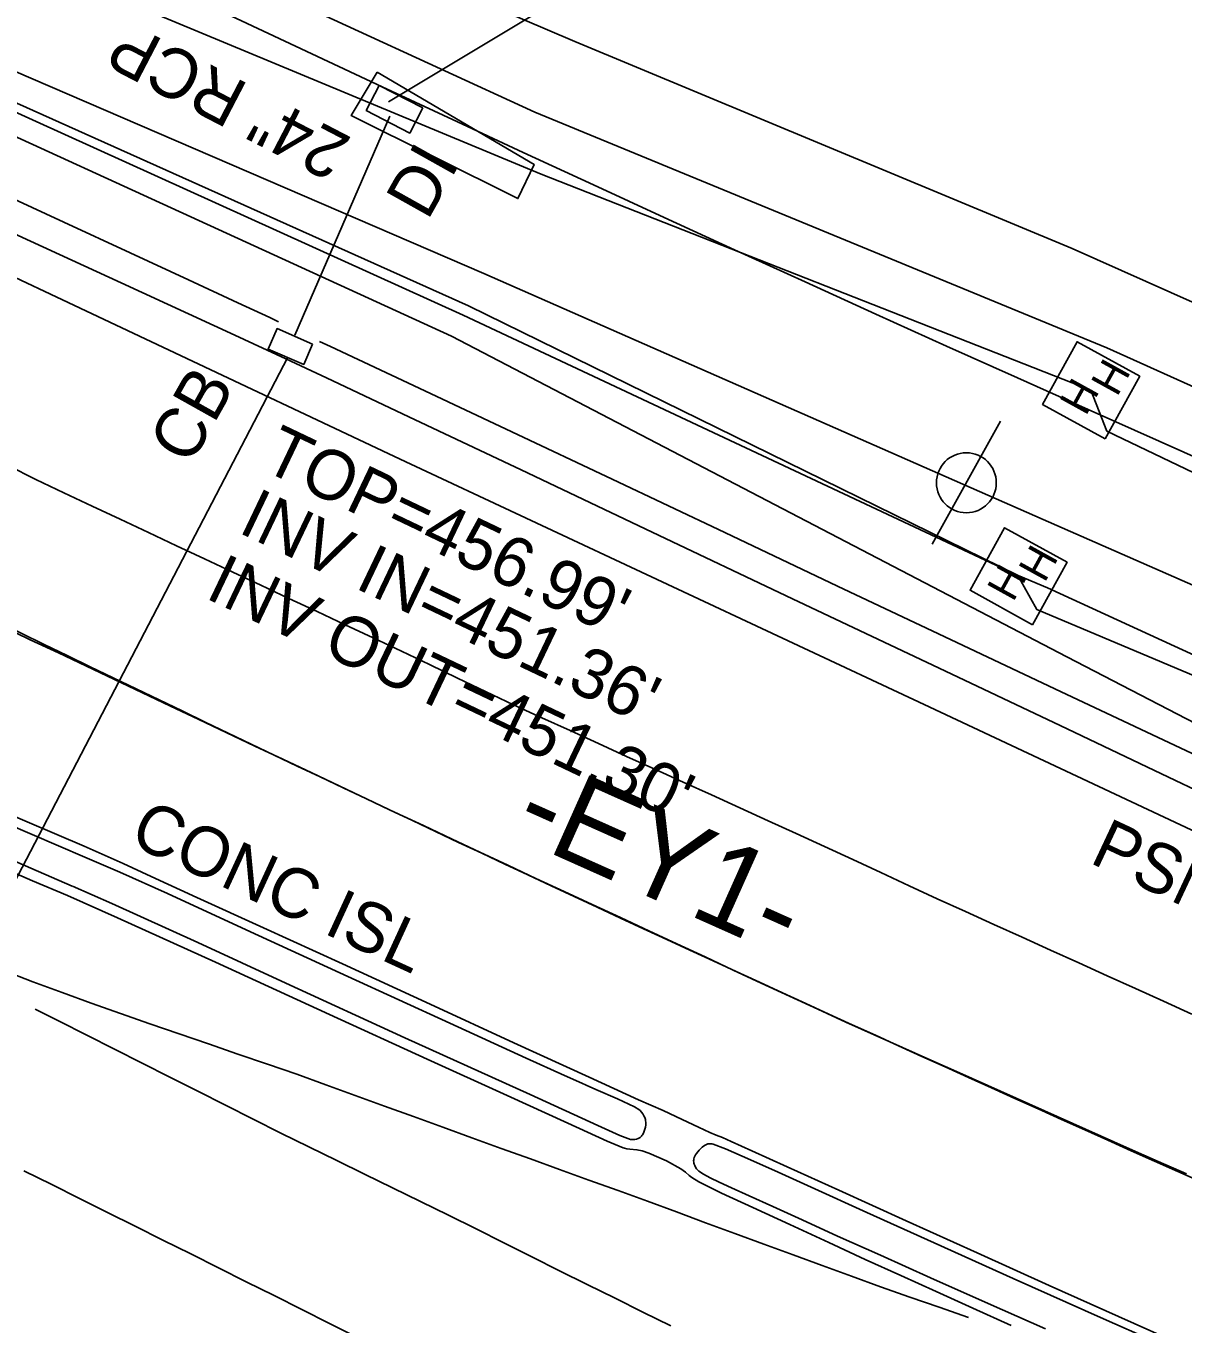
# Model space of a CAD drawing. Extents: x 2074109 to 2077820, y 741079 to 746031.
# Drawn here: x 2076288.2 to 2076381.3, y 742928.4 to 743032.9 of the extents above; entities that cross this region are included whole.
import ezdxf

# ---------------------------------------------------------------- set-up
doc = ezdxf.new("R2010")
doc.units = 0
for name, color, linetype in [('Exist Horizontal Alignment', 7, 'Continuous'), ('Exist Horizontal Alignment Direction Label', 7, 'Continuous'), ('Exist Right of Way Line', 7, 'Continuous'), ('Exist Roads Curbs', 7, 'Continuous'), ('Exist Roads Curbs Text', 7, 'Continuous'), ('Exist Roads EOP', 7, 'Continuous'), ('Exist Roads EOT', 7, 'Continuous'), ('Exist Structure Minor Catch Basin', 7, 'Continuous'), ('Exist Structure Minor Catch Basin Text', 7, 'Continuous'), ('Exist Structure Minor Catch Basin Top Elevation', 7, 'Continuous'), ('Exist Structure Minor Drop Inlet', 7, 'Continuous'), ('Exist Structure Minor Drop Inlet Text', 7, 'Continuous'), ('Exist Structure Minor Paved Ditch or Gutter', 7, 'Continuous'), ('Exist Structure Minor Pipes RCP 24 Inch', 7, 'Continuous'), ('Exist Structure Minor Pipes RCP 24 Inch Invert', 7, 'Continuous'), ('Exist Structure Minor Pipes RCP 24 Inch Text', 7, 'Continuous'), ('Exist Utilities Gas UG Line SUE LOS B', 7, 'Continuous'), ('Exist Utilities Gas UG Line SUE LOS B Text', 7, 'Continuous'), ('Exist Utilities Telephone Pole CELL', 7, 'Continuous'), ('Exist Utilities Telephone UG Conduit SUE LOS B', 7, 'Continuous'), ('Exist Utilities Telephone UG FO SUE LOS B', 7, 'Continuous'), ('Exist Utilities TV Hand Hole CELL', 7, 'Continuous'), ('Exist Utilities TV UG FO Cable SUE LOS B', 7, 'Continuous'), ('Exist Utilities Water UG Line SUE LOS B', 7, 'Continuous'), ('Exist Vegetation Woods Line', 7, 'Continuous')]:
    doc.layers.add(name, color=color, linetype=linetype)

msp = doc.modelspace()

# ---------------------------------------------------------------- linework, layer by layer
at = {"layer": 'Exist Horizontal Alignment'}
msp.add_arc((2077613.64, 745710.8), 3032.01, 242.28476, 247.25119, dxfattribs=at)
at = {"layer": 'Exist Right of Way Line'}
msp.add_arc((2077913.16, 746443.07), 3769.72, 244.28216, 256.42986, dxfattribs=at)
at = {"layer": 'Exist Roads Curbs'}
for points in [[(2076235.65, 743042.63), (2076239.67, 743040.81), (2076244.47, 743038.62), (2076249.87, 743036.16), (2076255.89, 743033.4), (2076262.45, 743030.39), (2076269.51, 743027.14), (2076276.98, 743023.7), (2076284.65, 743020.16), (2076291.22, 743017.13), (2076296.58, 743014.66), (2076301.26, 743012.49), (2076305.24, 743010.63), (2076307.8, 743009.44), (2076308.49, 743009.11)], [(2076311.8, 743007.53), (2076312.68, 743007.11), (2076319.83, 743003.76), (2076327.27, 743000.26), (2076335.35, 742996.45), (2076344.42, 742992.14), (2076353.49, 742987.83), (2076361.6, 742983.99), (2076370.97, 742979.57), (2076383.84, 742973.49), (2076398.38, 742966.6), (2076412.77, 742959.77), (2076426.42, 742953.29), (2076432.74, 742950.29), (2076446.25, 742943.92), (2076453.23, 742940.64)], [(2076286.55, 742968.75), (2076292.93, 742966.02), (2076295.74, 742964.81), (2076299.58, 742963.08), (2076306.25, 742960.01), (2076314.08, 742956.41), (2076322.29, 742952.64), (2076328.42, 742949.84), (2076331.51, 742948.44), (2076332.92, 742947.81), (2076333.27, 742947.65), (2076334.04, 742947.32), (2076335.77, 742946.56), (2076337.15, 742945.91), (2076337.5, 742945.7), (2076337.59, 742945.62), (2076337.71, 742945.49), (2076337.81, 742945.35), (2076337.9, 742945.2), (2076337.97, 742945.05), (2076338, 742944.98), (2076338.02, 742944.9), (2076338.04, 742944.82), (2076338.05, 742944.65), (2076338.05, 742944.47), (2076338.02, 742944.29), (2076337.98, 742944.12), (2076337.93, 742943.95), (2076337.87, 742943.81), (2076337.79, 742943.67), (2076337.75, 742943.61), (2076337.7, 742943.55), (2076337.66, 742943.5), (2076337.6, 742943.46), (2076337.55, 742943.42), (2076337.49, 742943.39), (2076337.43, 742943.36), (2076337.3, 742943.32), (2076337.17, 742943.29), (2076337.04, 742943.28), (2076336.92, 742943.28), (2076336.83, 742943.3), (2076335.98, 742943.62), (2076334.21, 742944.41), (2076328.74, 742946.9), (2076318.66, 742951.48), (2076309.09, 742955.87), (2076302.01, 742959.15), (2076295.08, 742962.29), (2076291.92, 742963.68)], [(2076291.91, 742963.68), (2076285.23, 742966.57)], [(2076382.65, 742925.41), (2076374.88, 742928.86), (2076367.61, 742932.11), (2076361.27, 742934.96), (2076355.84, 742937.41), (2076351.35, 742939.45), (2076348.71, 742940.65), (2076346.47, 742941.66), (2076344.47, 742942.53), (2076343.48, 742942.91), (2076343.37, 742942.94), (2076343.33, 742942.95), (2076343.3, 742942.95), (2076343.24, 742942.95), (2076343.18, 742942.95), (2076343.12, 742942.94), (2076343.06, 742942.93), (2076342.94, 742942.89), (2076342.82, 742942.83), (2076342.7, 742942.75), (2076342.58, 742942.66), (2076342.34, 742942.42), (2076342.14, 742942.17), (2076342.06, 742942.05), (2076342, 742941.94), (2076341.95, 742941.84), (2076341.92, 742941.74), (2076341.91, 742941.69), (2076341.91, 742941.65), (2076341.9, 742941.56), (2076341.91, 742941.47), (2076341.93, 742941.38), (2076341.95, 742941.29), (2076341.99, 742941.2), (2076342.03, 742941.11), (2076342.14, 742940.94), (2076342.22, 742940.84), (2076342.33, 742940.74), (2076342.69, 742940.49), (2076343.23, 742940.2), (2076343.96, 742939.85), (2076344.94, 742939.4), (2076346.38, 742938.75), (2076348.27, 742937.89), (2076350.63, 742936.81), (2076353.49, 742935.52), (2076356.93, 742933.97), (2076360.97, 742932.16), (2076365.6, 742930.1), (2076370.23, 742928.04)]]:
    msp.add_lwpolyline(points, dxfattribs=at)
at = {"layer": 'Exist Roads EOP'}
for points in [[(2076235.2, 743040.06), (2076241.92, 743037.01), (2076248.79, 743033.9), (2076256.2, 743030.54), (2076264.49, 743026.73), (2076274.02, 743022.31), (2076284.56, 743017.43), (2076295.85, 743012.23), (2076304.99, 743008.03), (2076309.1, 743006.12), (2076312.36, 743004.59), (2076318.98, 743001.47), (2076328.02, 742997.2), (2076338.57, 742992.18), (2076349.87, 742986.8), (2076361.16, 742981.46), (2076371.4, 742976.61), (2076379.55, 742972.73), (2076387.23, 742969.07)], [(2076281.29, 742971.87), (2076288.28, 742968.86), (2076292.86, 742966.89), (2076296, 742965.5), (2076298.26, 742964.47), (2076301.94, 742962.78), (2076307.3, 742960.33), (2076313.65, 742957.42), (2076320.7, 742954.18), (2076327.44, 742951.08), (2076333.49, 742948.3), (2076337.48, 742946.48), (2076339.45, 742945.61), (2076340.98, 742944.9), (2076342.29, 742944.27), (2076343.2, 742943.86), (2076343.72, 742943.65), (2076344.23, 742943.44), (2076344.93, 742943.13), (2076346.6, 742942.37), (2076349.42, 742941.09), (2076353.6, 742939.2), (2076359.01, 742936.75), (2076364.72, 742934.17), (2076370.52, 742931.55), (2076376.09, 742929.04), (2076381.37, 742926.68)], [(2076367.46, 742928.33), (2076364.37, 742929.72), (2076361.43, 742931.05), (2076358.57, 742932.34), (2076355.72, 742933.64), (2076352.78, 742934.99), (2076349.65, 742936.44), (2076346.66, 742937.82), (2076344.16, 742938.97), (2076342.33, 742939.88), (2076341.75, 742940.23), (2076341.55, 742940.39), (2076341.25, 742940.66), (2076340.87, 742940.94), (2076339.71, 742941.58), (2076338.3, 742942.19), (2076337.76, 742942.37), (2076337.34, 742942.47), (2076336.76, 742942.51), (2076336.53, 742942.54), (2076336.33, 742942.58), (2076336.24, 742942.61), (2076334.96, 742943.16), (2076331.79, 742944.59), (2076326.91, 742946.82), (2076320.47, 742949.76), (2076312.6, 742953.36), (2076303.43, 742957.55), (2076295.55, 742961.14), (2076291.53, 742962.92), (2076288.72, 742964.12), (2076284.44, 742965.95)]]:
    msp.add_lwpolyline(points, dxfattribs=at)
at = {"layer": 'Exist Roads EOT'}
for points in [[(2076382, 742953.37), (2076379.72, 742954.41), (2076377.45, 742955.44), (2076375.17, 742956.47), (2076372.89, 742957.5), (2076370.62, 742958.54), (2076368.34, 742959.57), (2076366.06, 742960.6), (2076363.79, 742961.64), (2076361.51, 742962.67), (2076359.24, 742963.71), (2076356.97, 742964.77), (2076354.71, 742965.82), (2076352.44, 742966.87), (2076350.16, 742967.91), (2076347.89, 742968.94), (2076345.61, 742969.98), (2076343.34, 742971.02), (2076341.06, 742972.05), (2076338.79, 742973.09), (2076336.51, 742974.13), (2076334.24, 742975.16), (2076331.96, 742976.2), (2076329.69, 742977.24), (2076327.42, 742978.27), (2076325.15, 742979.34), (2076322.9, 742980.42), (2076320.65, 742981.51), (2076318.4, 742982.59), (2076316.13, 742983.66), (2076313.87, 742984.72), (2076311.61, 742985.78), (2076309.34, 742986.84), (2076307.08, 742987.9), (2076304.82, 742988.96), (2076302.55, 742990.02), (2076300.29, 742991.08), (2076298.03, 742992.14), (2076295.76, 742993.21), (2076293.5, 742994.27), (2076291.23, 742995.33), (2076288.98, 742996.42), (2076286.75, 742997.53)], [(2076381.56, 742940.52), (2076379.27, 742941.53), (2076376.99, 742942.55), (2076374.71, 742943.57), (2076372.42, 742944.58), (2076370.14, 742945.6), (2076367.86, 742946.62), (2076365.57, 742947.63), (2076363.29, 742948.65), (2076361, 742949.67), (2076358.72, 742950.69), (2076356.44, 742951.71), (2076354.16, 742952.74), (2076351.89, 742953.77), (2076349.62, 742954.82), (2076347.35, 742955.88), (2076345.09, 742956.93), (2076342.82, 742957.99), (2076340.55, 742959.04), (2076338.29, 742960.09), (2076336.02, 742961.15), (2076333.75, 742962.2), (2076331.49, 742963.26), (2076329.22, 742964.31), (2076326.95, 742965.37), (2076324.69, 742966.42), (2076322.42, 742967.49), (2076320.16, 742968.55), (2076317.9, 742969.61), (2076315.64, 742970.68), (2076313.38, 742971.75), (2076311.12, 742972.82), (2076308.86, 742973.89), (2076306.6, 742974.96), (2076304.34, 742976.03), (2076302.08, 742977.1), (2076299.82, 742978.17), (2076297.56, 742979.24), (2076295.31, 742980.31), (2076293.05, 742981.38), (2076290.79, 742982.45), (2076288.53, 742983.52), (2076286.27, 742984.6)], [(2076364.03, 742928.96), (2076361.67, 742929.78), (2076359.31, 742930.6), (2076356.95, 742931.42), (2076354.6, 742932.28), (2076352.25, 742933.14), (2076349.91, 742934), (2076347.56, 742934.86), (2076345.21, 742935.73), (2076342.87, 742936.59), (2076340.52, 742937.46), (2076338.18, 742938.32), (2076335.83, 742939.18), (2076333.48, 742940.02), (2076331.12, 742940.87), (2076328.77, 742941.72), (2076326.42, 742942.57), (2076324.07, 742943.41), (2076321.72, 742944.27), (2076319.37, 742945.13), (2076317.02, 742945.98), (2076314.67, 742946.84), (2076312.32, 742947.69), (2076309.97, 742948.54), (2076307.61, 742949.35), (2076305.24, 742950.17), (2076302.88, 742950.98), (2076300.52, 742951.79), (2076298.15, 742952.61), (2076295.79, 742953.42), (2076293.44, 742954.26), (2076291.09, 742955.13), (2076288.74, 742955.99), (2076286.41, 742956.9)], [(2076340.07, 742928.28), (2076337.83, 742929.39), (2076335.59, 742930.51), (2076333.35, 742931.62), (2076331.11, 742932.73), (2076328.88, 742933.85), (2076326.64, 742934.97), (2076324.41, 742936.09), (2076322.17, 742937.2), (2076319.93, 742938.31), (2076317.68, 742939.41), (2076315.43, 742940.5), (2076313.19, 742941.6), (2076310.94, 742942.69), (2076308.7, 742943.81), (2076306.47, 742944.93), (2076304.23, 742946.05), (2076302, 742947.17), (2076299.77, 742948.3), (2076297.54, 742949.43), (2076295.31, 742950.55), (2076293.08, 742951.68), (2076290.85, 742952.81), (2076288.93, 742953.78)], [(2076314.85, 742927.36), (2076312.61, 742928.48), (2076310.38, 742929.6), (2076308.15, 742930.72), (2076305.91, 742931.84), (2076303.67, 742932.96), (2076301.44, 742934.08), (2076299.2, 742935.19), (2076296.97, 742936.31), (2076294.73, 742937.42), (2076292.49, 742938.54), (2076290.26, 742939.66), (2076288.02, 742940.77)]]:
    msp.add_lwpolyline(points, dxfattribs=at)
at = {"layer": 'Exist Structure Minor Catch Basin'}
msp.add_lwpolyline([(2076311.24, 743007.31), (2076308.39, 743008.56), (2076307.67, 743006.91), (2076310.53, 743005.67)], close=True, dxfattribs=at)
at = {"layer": 'Exist Structure Minor Drop Inlet'}
msp.add_lwpolyline([(2076320.11, 743026.32), (2076316.61, 743028.14), (2076315.56, 743026.12), (2076319.06, 743024.3)], close=True, dxfattribs=at)
at = {"layer": 'Exist Structure Minor Paved Ditch or Gutter'}
msp.add_lwpolyline([(2076316.43, 743029.19), (2076329.07, 743021.78), (2076327.76, 743019.03), (2076314.36, 743025.7), (2076316.43, 743029.19)], dxfattribs=at)
at = {"layer": 'Exist Structure Minor Pipes RCP 24 Inch'}
for p, q in [((2076376.04, 743062.08), (2076317.35, 743026.81)), ((2076317.45, 743025.66), (2076309.81, 743008.03)), ((2076309.25, 743006.26), (2076261.02, 742913.6))]:
    msp.add_line(p, q, dxfattribs=at)
at = {"layer": 'Exist Utilities Gas UG Line SUE LOS B'}
msp.add_lwpolyline([(2075996.08, 743328.1), (2076028.05, 743254.56), (2076033.74, 743242.95), (2076036.74, 743229.04), (2076040.38, 743218.46), (2076044.43, 743205.24), (2076049.54, 743192.7), (2076055.99, 743180.15), (2076059.89, 743167.76), (2076068.56, 743138.12), (2076068.53, 743138.04), (2076073.69, 743123.02), (2076077.5, 743117.33), (2076094.04, 743108.87), (2076148.84, 743082.51), (2076220.11, 743045.2), (2076259.6, 743025.74), (2076318.3, 742998.06), (2076360.46, 742978.31), (2076403.47, 742958.09), (2076437.14, 742944.03)], dxfattribs=at)
at = {"layer": 'Exist Utilities Telephone Pole CELL'}
for p, q in [((2076361.09, 742991.2), (2076366.61, 743001.1)), ((2076363.85, 742996.15), (2076363.85, 742996.15))]:
    msp.add_line(p, q, dxfattribs=at)
msp.add_circle((2076363.85, 742996.15), 2.41, dxfattribs=at)
at = {"layer": 'Exist Utilities Telephone UG Conduit SUE LOS B'}
msp.add_lwpolyline([(2075672.89, 743341.39), (2075736.54, 743308.65), (2075796.69, 743278.05), (2075867.04, 743238.5), (2075921.9, 743209.46), (2075960.48, 743187.73), (2076008.51, 743166.58), (2076026.12, 743160.68), (2076048.83, 743145.45), (2076053.46, 743153.14), (2076083.51, 743134.83), (2076100.14, 743126.62), (2076153.6, 743096.75), (2076227.57, 743057.65), (2076265.35, 743038.75), (2076325.02, 743012.99), (2076370.03, 742993.2), (2076407.51, 742976.75), (2076444.05, 742959.06)], dxfattribs=at)
at = {"layer": 'Exist Utilities Telephone UG FO SUE LOS B'}
msp.add_lwpolyline([(2075889.86, 743237.93), (2075895.59, 743228.51), (2075924.94, 743209.93), (2075958.41, 743190.94), (2075991.59, 743174.52), (2076008.89, 743165.82), (2076027.41, 743153.76), (2076049.09, 743142.61), (2076053.91, 743141.46), (2076059.01, 743140.99), (2076072.19, 743141.15), (2076089.2, 743137.48), (2076101.24, 743131.5), (2076156.95, 743103.14), (2076158.66, 743102.38), (2076232.03, 743071), (2076268.38, 743053.9), (2076329.12, 743025.97), (2076375.16, 743007.01), (2076410.42, 742991.12), (2076450.75, 742973.66)], dxfattribs=at)
at = {"layer": 'Exist Utilities TV Hand Hole CELL'}
for p, q in [((2076373.89, 743003.59), (2076373.89, 743003.59)), ((2076368.05, 742988.62), (2076368.05, 742988.62))]:
    msp.add_line(p, q, dxfattribs=at)
for points in [[(2076375.02, 742999.68), (2076377.8, 743004.72), (2076372.76, 743007.5), (2076369.98, 743002.46), (2076375.02, 742999.68)], [(2076369.18, 742984.72), (2076371.96, 742989.75), (2076366.93, 742992.53), (2076364.15, 742987.5), (2076369.18, 742984.72)]]:
    msp.add_lwpolyline(points, dxfattribs=at)
at = {"layer": 'Exist Utilities TV UG FO Cable SUE LOS B'}
for points in [[(2076079.54, 743131.47), (2076088.75, 743134.71), (2076100.72, 743130.58), (2076230.37, 743064.49), (2076267.06, 743047.02), (2076329.64, 743021), (2076373.86, 743003.6), (2076375.16, 743000.31), (2076408.25, 742984.45), (2076447.17, 742965.86)], [(2076083.6, 743130.45), (2076090.74, 743121.86), (2076099.09, 743116.59), (2076149.07, 743090.83), (2076226.38, 743054.36), (2076264.41, 743037.05), (2076323.79, 743010.38), (2076368.03, 742988.68), (2076370.37, 742987.68), (2076405.31, 742971.65), (2076441.93, 742954.46)], [(2076083.6, 743130.45), (2076090.73, 743121.86), (2076098.84, 743116.1), (2076148.75, 743090.35), (2076226.27, 743053.92), (2076264.15, 743036.52), (2076323.36, 743009.63), (2076368, 742988.68), (2076369.51, 742985.96), (2076404.98, 742971), (2076441.71, 742953.97)]]:
    msp.add_lwpolyline(points, dxfattribs=at)
at = {"layer": 'Exist Utilities Water UG Line SUE LOS B'}
msp.add_lwpolyline([(2075822.78, 743289.56), (2075827.27, 743285.77), (2075840.04, 743277.92), (2075859.15, 743265.03), (2075885.55, 743248.54), (2075912.1, 743233.66), (2075938.18, 743219.55), (2075978.32, 743202.62), (2076004.37, 743190.72), (2076024.72, 743179.9), (2076058.28, 743162.37), (2076071.85, 743150.27), (2076099.45, 743125.15), (2076149.87, 743092.08), (2076225.21, 743053.38), (2076263, 743035.19), (2076322.41, 743007.95), (2076371.93, 742982.13), (2076406.73, 742964.12), (2076444.22, 742949.22), (2076483.69, 742930.03)], dxfattribs=at)
at = {"layer": 'Exist Vegetation Woods Line'}
msp.add_lwpolyline([(2076452.8, 742978.14), (2076411.57, 742997.51), (2076372.36, 743015), (2076332.34, 743031.67), (2076302.88, 743044.27), (2076275.96, 743054.74), (2076254.46, 743059.65), (2076231.08, 743070.25), (2076212.24, 743079.14), (2076197.2, 743091.07), (2076186.86, 743102.52), (2076184.31, 743113.37), (2076185.7, 743122.79), (2076183.65, 743131.36), (2076180.3, 743139.76), (2076155.91, 743151.77), (2076143.65, 743150.09), (2076137.94, 743137.99), (2076140.74, 743129.52), (2076148.47, 743119.68), (2076149.8, 743116.21), (2076142.91, 743116.48), (2076122.59, 743129.22), (2076117.94, 743141.67)], dxfattribs=at)

# ---------------------------------------------------------------- texts
at = {"layer": 'Exist Horizontal Alignment Direction Label'}
msp.add_text('-EY1-', height=7, rotation=335.9162, dxfattribs=at).set_placement((2076327.11, 742967.8))
at = {"layer": 'Exist Roads Curbs Text'}
msp.add_text('CONC ISL', height=4, rotation=335.3122, dxfattribs=at).set_placement((2076296.36, 742967.13))
at = {"layer": 'Exist Structure Minor Catch Basin Text'}
msp.add_text('CB', height=4, rotation=60.742, dxfattribs=at).set_placement((2076301.41, 742997.45))
at = {"layer": 'Exist Structure Minor Catch Basin Top Elevation'}
msp.add_text("TOP=456.99'", height=4, rotation=334.5204, dxfattribs=at).set_placement((2076307.03, 742997.28))
at = {"layer": 'Exist Structure Minor Drop Inlet Text'}
msp.add_text('DI', height=4, rotation=60.7411, dxfattribs=at).set_placement((2076320.49, 743017.18))
at = {"layer": 'Exist Structure Minor Pipes RCP 24 Inch Invert'}
for s, p in [("INV IN=451.36'", (2076305.15, 742992.2)), ("INV OUT=451.30'", (2076302.5, 742986.92))]:
    msp.add_text(s, height=4, rotation=334.5204, dxfattribs=at).set_placement(p)
at = {"layer": 'Exist Structure Minor Pipes RCP 24 Inch Text'}
msp.add_text('24" RCP', height=4, rotation=152.5265, dxfattribs=at).set_placement((2076314.52, 743023.86))
at = {"layer": 'Exist Utilities Gas UG Line SUE LOS B Text'}
msp.add_text('PSNC Energy, 12 ", STEEL', height=4, rotation=334.8952, dxfattribs=at).set_placement((2076373.66, 742965.61))
at = {"layer": 'Exist Utilities TV Hand Hole CELL'}
for p in [(2076375.97, 743003), (2076373.45, 743001.45), (2076370.14, 742988.03), (2076367.61, 742986.48)]:
    msp.add_text('H', height=2.5, rotation=61.1016, dxfattribs=at).set_placement(p)

doc.saveas('drawing.dxf')
